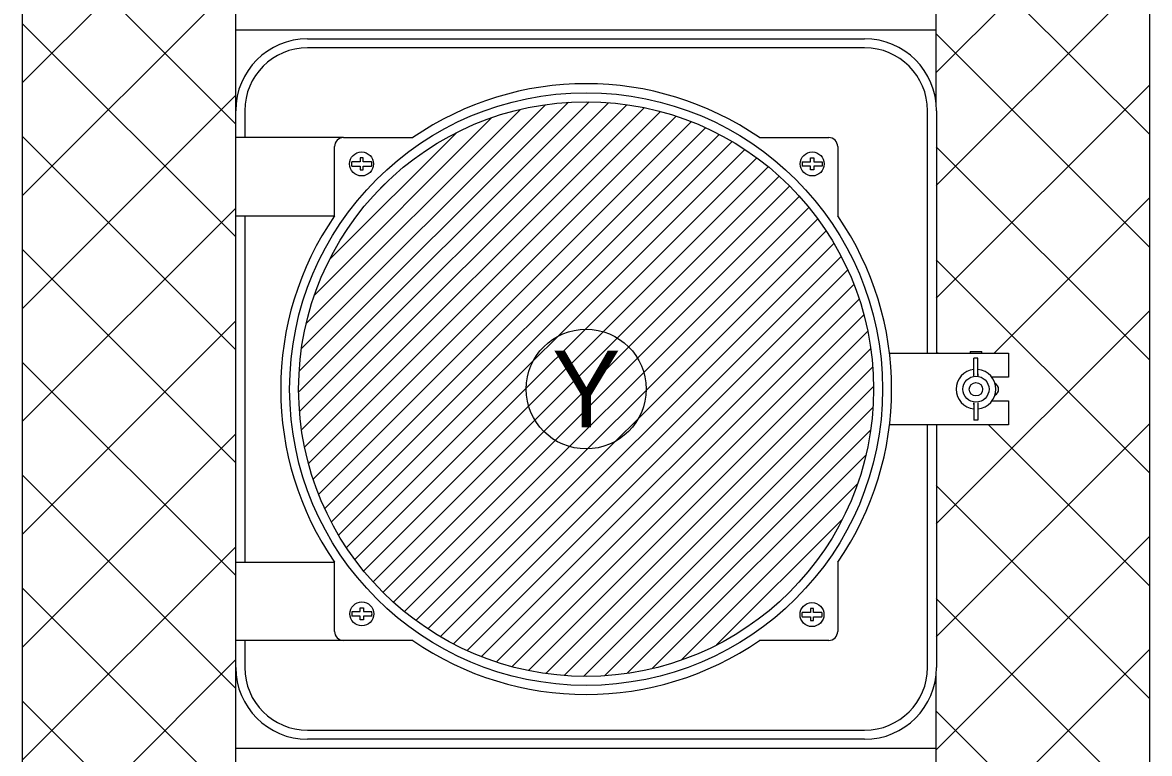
# Model space of a CAD drawing. Extents: x 99862 to 103680, y 99470 to 105076.
# Drawn here: x 101307.4 to 101519.1, y 104763.1 to 104900.5 of the extents above; entities that cross this region are included whole.
import ezdxf

# ---------------------------------------------------------------- set-up
doc = ezdxf.new("R2010")
doc.units = 0
for name, color, linetype in [('Level 1', 7, 'Continuous'), ('Level 12', 7, 'Continuous'), ('Level 18', 7, 'Continuous'), ('Level 20', 7, 'Continuous'), ('Level 4', 7, 'Continuous')]:
    doc.layers.add(name, color=color, linetype=linetype)

msp = doc.modelspace()

# ---------------------------------------------------------------- linework, layer by layer
at = {"layer": 'Level 1'}
for p, q in [((101307.44, 104609.1), (101307.44, 105054.1)), ((101519.12, 105054.1), (101519.12, 104609.1)), ((101347.44, 105034.1), (101347.44, 104629.1)), ((101307.44, 104889.18), (101347.44, 104929.18)), ((101479.07, 104891.1), (101519.12, 104931.15)), ((101347.44, 104881.46), (101307.44, 104921.46)), ((101519.12, 104879.49), (101479.07, 104919.54)), ((101479.07, 104899.1), (101479.07, 104913.14)), ((101307.44, 104867.97), (101347.44, 104907.97)), ((101479.07, 104869.88), (101519.12, 104909.93)), ((101347.44, 104860.25), (101307.44, 104900.25)), ((101347.44, 104899.1), (101479.07, 104899.1)), ((101360.99, 104897.41), (101465.62, 104897.41)), ((101479.07, 104885.06), (101479.07, 104899.1)), ((101519.12, 104858.28), (101479.07, 104898.33)), ((101465.62, 104895.73), (101360.99, 104895.73)), ((101307.44, 104846.75), (101347.44, 104886.75)), ((101479.07, 104848.67), (101519.12, 104888.72)), ((101349.18, 104883.91), (101349.18, 104878.85)), ((101477.43, 104838.35), (101477.43, 104883.91)), ((101479.12, 104883.91), (101479.12, 104838.35)), ((101347.44, 104839.03), (101307.44, 104879.03)), ((101367.74, 104878.85), (101347.44, 104878.85)), ((101367.74, 104878.85), (101380.76, 104878.85)), ((101445.85, 104878.85), (101458.87, 104878.85)), ((101366.06, 104864.15), (101366.06, 104877.16)), ((101460.56, 104877.16), (101460.56, 104864.15)), ((101519.12, 104837.07), (101479.07, 104877.12)), ((101489.96, 104838.35), (101519.12, 104867.51)), ((101307.44, 104825.54), (101347.44, 104865.54)), ((101347.44, 104864.15), (101366.06, 104864.15)), ((101349.18, 104864.15), (101349.18, 104799.05)), ((101347.44, 104817.82), (101307.44, 104857.82)), ((101519.12, 104815.85), (101479.07, 104855.9)), ((101479.07, 104806.25), (101519.12, 104846.29)), ((101307.44, 104804.33), (101347.44, 104844.33)), ((101470.28, 104838.35), (101478.24, 104838.35)), ((101478.31, 104838.35), (101492.62, 104838.35)), ((101479.12, 104838.4), (101479.24, 104838.4)), ((101479.24, 104838.35), (101479.24, 104838.4)), ((101479.24, 104838.4), (101479.4, 104838.4)), ((101479.4, 104838.35), (101479.4, 104838.4)), ((101480.88, 104838.35), (101480.88, 104838.4)), ((101492.6, 104838.35), (101492.6, 104838.4)), ((101492.62, 104838.35), (101492.62, 104833.85)), ((101347.44, 104796.61), (101307.44, 104836.61)), ((101492.62, 104833.85), (101489.48, 104833.85)), ((101489.57, 104829.4), (101492.62, 104829.4)), ((101492.62, 104829.4), (101492.62, 104824.85)), ((101478.24, 104824.85), (101470.28, 104824.85)), ((101477.43, 104779.29), (101477.43, 104824.85)), ((101492.62, 104824.85), (101478.31, 104824.85)), ((101479.07, 104785.03), (101519.12, 104825.08)), ((101479.12, 104824.85), (101479.12, 104779.29)), ((101519.12, 104794.64), (101488.91, 104824.85)), ((101307.44, 104783.11), (101347.44, 104823.11)), ((101347.44, 104775.39), (101307.44, 104815.39)), ((101519.12, 104773.43), (101479.07, 104813.48)), ((101479.07, 104763.82), (101519.12, 104803.87)), ((101307.44, 104761.9), (101347.44, 104801.9)), ((101347.44, 104799.05), (101366.06, 104799.05)), ((101366.06, 104786.04), (101366.06, 104799.05)), ((101460.56, 104799.05), (101460.56, 104786.04)), ((101347.44, 104754.18), (101307.44, 104794.18)), ((101519.12, 104752.21), (101479.07, 104792.26)), ((101367.74, 104784.35), (101347.44, 104784.35)), ((101349.18, 104784.35), (101349.18, 104779.29)), ((101380.76, 104784.35), (101367.74, 104784.35)), ((101458.87, 104784.35), (101445.85, 104784.35)), ((101479.07, 104742.61), (101519.12, 104782.65)), ((101307.44, 104740.69), (101347.44, 104780.69)), ((101479.07, 104764.1), (101479.07, 104778.14)), ((101347.44, 104732.97), (101307.44, 104772.97)), ((101519.12, 104731), (101479.07, 104771.05)), ((101360.99, 104767.48), (101465.62, 104767.48)), ((101347.44, 104764.1), (101479.07, 104764.1)), ((101465.62, 104765.79), (101360.99, 104765.79)), ((101479.07, 104750.06), (101479.07, 104764.1))]:
    msp.add_line(p, q, dxfattribs=at)
for radius in [55.69, 54]:
    msp.add_circle((101413.31, 104831.6), radius, dxfattribs=at)
for centre, radius, start, end in [((101360.99, 104883.91), 13.5, 90, 180), ((101465.62, 104883.91), 13.5, 0, 90), ((101360.99, 104883.91), 11.81, 90, 180), ((101465.62, 104883.91), 11.81, 0, 90), ((101413.31, 104831.6), 57.38, 55.4397, 124.5603), ((101367.74, 104877.16), 1.69, 90, 180), ((101458.87, 104877.16), 1.69, 0, 90), ((101413.31, 104831.6), 57.38, 145.4397, 214.5603), ((101413.31, 104831.6), 57.38, 325.4397, 34.5603), ((101367.74, 104786.04), 1.69, 180, 270), ((101458.87, 104786.04), 1.69, 270, 0), ((101413.31, 104831.6), 57.38, 235.4397, 304.5603), ((101360.99, 104779.29), 13.5, 180, 270), ((101360.99, 104779.29), 11.81, 180, 270), ((101465.62, 104779.29), 13.5, 270, 0), ((101465.62, 104779.29), 11.81, 270, 0)]:
    msp.add_arc(centre, radius, start, end, dxfattribs=at)
at = {"layer": 'Level 12'}
for p, q in [((101359.31, 104831.02), (101413.88, 104885.59)), ((101359.42, 104834.95), (101409.97, 104885.5)), ((101359.48, 104827.37), (101417.52, 104885.41)), ((101359.86, 104823.93), (101420.96, 104885.03)), ((101359.87, 104839.21), (101405.7, 104885.04)), ((101360.43, 104820.68), (101424.21, 104884.46)), ((101360.74, 104843.91), (101400.99, 104884.15)), ((101361.16, 104817.59), (101427.3, 104883.73)), ((101362.04, 104814.66), (101430.24, 104882.85)), ((101362.32, 104849.29), (101395.62, 104882.6)), ((101363.07, 104811.86), (101433.05, 104881.84)), ((101364.21, 104809.18), (101435.74, 104880.71)), ((101365.12, 104855.92), (101388.99, 104879.79)), ((101365.46, 104806.62), (101438.3, 104879.46)), ((101366.82, 104804.16), (101440.75, 104878.09)), ((101368.28, 104801.8), (101443.09, 104876.61)), ((101369.85, 104799.56), (101445.34, 104875.04)), ((101371.53, 104797.42), (101447.5, 104873.38)), ((101373.3, 104795.37), (101449.56, 104871.62)), ((101374.22, 104868.84), (101376.33, 104870.94)), ((101375.16, 104793.41), (101451.5, 104869.75)), ((101377.11, 104791.54), (101453.35, 104867.78)), ((101379.17, 104789.78), (101455.12, 104865.73)), ((101381.33, 104788.12), (101456.8, 104863.59)), ((101383.58, 104786.55), (101458.37, 104861.34)), ((101385.93, 104785.08), (101459.83, 104858.98)), ((101388.37, 104783.71), (101461.18, 104856.52)), ((101390.94, 104782.46), (101462.43, 104853.95)), ((101393.63, 104781.33), (101463.57, 104851.27)), ((101396.44, 104780.33), (101464.59, 104848.47)), ((101399.39, 104779.45), (101465.47, 104845.54)), ((101402.48, 104778.73), (101466.2, 104842.45)), ((101405.73, 104778.16), (101466.76, 104839.19)), ((101409.18, 104777.79), (101467.14, 104835.75)), ((101412.82, 104777.61), (101467.3, 104832.09)), ((101416.74, 104777.71), (101467.18, 104828.15)), ((101421.02, 104778.18), (101466.72, 104823.88)), ((101425.74, 104779.08), (101465.84, 104819.18)), ((101431.14, 104780.66), (101464.25, 104813.76)), ((101437.81, 104783.51), (101461.4, 104807.1))]:
    msp.add_line(p, q, dxfattribs=at)
at = {"layer": 'Level 18'}
msp.add_circle((101413.31, 104831.6), 11.25, dxfattribs=at)
at = {"layer": 'Level 4'}
for p, q in [((101485.42, 104838.63), (101487.64, 104838.63)), ((101485.42, 104838.63), (101485.42, 104838.4)), ((101487.64, 104838.63), (101487.64, 104838.63)), ((101487.64, 104838.4), (101487.64, 104838.63)), ((101486.15, 104835.54), (101486.15, 104837.38)), ((101486.91, 104837.38), (101486.15, 104837.38)), ((101486.91, 104835.54), (101486.91, 104837.38)), ((101486.15, 104834.73), (101486.15, 104835.54)), ((101486.15, 104834.14), (101486.15, 104834.73)), ((101486.91, 104834.73), (101486.91, 104835.54)), ((101486.91, 104834.14), (101486.91, 104834.73)), ((101486.15, 104829), (101486.15, 104828.4)), ((101486.15, 104828.4), (101486.15, 104827.59)), ((101486.15, 104827.59), (101486.15, 104825.75)), ((101486.91, 104829), (101486.91, 104828.4)), ((101486.91, 104828.4), (101486.91, 104827.59)), ((101486.91, 104827.59), (101486.91, 104825.75)), ((101486.91, 104825.75), (101486.15, 104825.75))]:
    msp.add_line(p, q, dxfattribs=at)
for centre, radius in [((101371.13, 104873.9), 2.25), ((101455.78, 104873.9), 2.25), ((101486.53, 104831.57), 2.45), ((101486.53, 104831.55), 1.25), ((101371.18, 104789.35), 2.25), ((101455.73, 104789.21), 2.25)]:
    msp.add_circle(centre, radius, dxfattribs=at)
for centre, radius, start, end in [((101371.13, 104873.9), 1.91, 167.4639, 192.4931), ((101371.13, 104873.9), 1.91, 347.5069, 12.5361), ((101455.78, 104873.9), 1.91, 167.4639, 192.4931), ((101455.78, 104873.9), 1.91, 347.5069, 12.5361), ((101486.53, 104831.57), 3.73, 95.8352, 264.1648), ((101486.53, 104831.57), 2.89, 97.5642, 97.5998), ((101486.53, 104831.57), 3.73, 275.8352, 84.1648), ((101486.53, 104831.57), 2.89, 82.4002, 82.4567), ((101489.54, 104831.55), 1.25, 295.8954, 63.3748), ((101486.53, 104831.57), 2.89, 262.4002, 262.4483), ((101486.53, 104831.57), 2.89, 277.5551, 277.5998), ((101371.18, 104789.35), 1.91, 167.5069, 192.5361), ((101371.18, 104789.35), 1.91, 347.4639, 12.4931), ((101455.73, 104789.21), 1.91, 167.5069, 192.5361), ((101455.73, 104789.21), 1.91, 347.4639, 12.4931)]:
    msp.add_arc(centre, radius, start, end, dxfattribs=at)
for points, degree in [([(101370.84, 104874.31), (101370.8, 104874.31), (101370.76, 104874.31), (101370.71, 104874.31), (101370.44, 104874.31), (101370.16, 104874.31), (101369.9, 104874.31), (101369.67, 104874.31), (101369.45, 104874.31), (101369.27, 104874.31)], 3), ([(101371.44, 104875.02), (101371.34, 104875.02), (101371.24, 104875.02), (101371.14, 104875.02), (101371.04, 104875.02), (101370.94, 104875.02), (101370.84, 104875.02)], 3), ([(101370.84, 104875.02), (101370.84, 104874.92), (101370.84, 104874.81), (101370.84, 104874.69), (101370.84, 104874.57), (101370.84, 104874.44), (101370.84, 104874.31)], 3), ([(101371.44, 104874.31), (101371.44, 104874.55), (101371.44, 104874.8), (101371.44, 104875.02)], 2), ([(101372.99, 104874.31), (101372.85, 104874.31), (101372.68, 104874.31), (101372.5, 104874.31), (101372.28, 104874.31), (101372.04, 104874.31), (101371.8, 104874.31), (101371.68, 104874.31), (101371.56, 104874.31), (101371.44, 104874.31)], 3), ([(101453.91, 104874.31), (101454.06, 104874.31), (101454.23, 104874.31), (101454.4, 104874.31), (101454.62, 104874.31), (101454.86, 104874.31), (101455.11, 104874.31), (101455.23, 104874.31), (101455.35, 104874.31), (101455.47, 104874.31)], 3), ([(101455.47, 104874.31), (101455.47, 104874.55), (101455.47, 104874.8), (101455.47, 104875.02)], 2), ([(101455.47, 104875.02), (101455.57, 104875.02), (101455.67, 104875.02), (101455.77, 104875.02), (101455.87, 104875.02), (101455.97, 104875.02), (101456.07, 104875.02)], 3), ([(101456.07, 104875.02), (101456.07, 104874.92), (101456.07, 104874.81), (101456.07, 104874.69), (101456.07, 104874.57), (101456.07, 104874.44), (101456.07, 104874.31)], 3), ([(101456.07, 104874.31), (101456.11, 104874.31), (101456.15, 104874.31), (101456.19, 104874.31), (101456.47, 104874.31), (101456.75, 104874.31), (101457, 104874.31), (101457.24, 104874.31), (101457.46, 104874.31), (101457.64, 104874.31)], 3), ([(101369.27, 104873.49), (101369.41, 104873.49), (101369.57, 104873.49), (101369.75, 104873.49), (101369.97, 104873.49), (101370.21, 104873.49), (101370.46, 104873.49), (101370.58, 104873.49), (101370.71, 104873.49), (101370.84, 104873.49)], 3), ([(101370.84, 104873.49), (101370.84, 104873.24), (101370.84, 104873), (101370.84, 104872.77)], 2), ([(101370.84, 104872.77), (101370.94, 104872.77), (101371.04, 104872.77), (101371.14, 104872.77), (101371.24, 104872.77), (101371.34, 104872.77), (101371.44, 104872.77)], 3), ([(101371.44, 104873.49), (101371.47, 104873.49), (101371.51, 104873.49), (101371.54, 104873.49), (101371.82, 104873.49), (101372.1, 104873.49), (101372.35, 104873.49), (101372.59, 104873.49), (101372.81, 104873.49), (101372.99, 104873.49)], 3), ([(101371.44, 104872.77), (101371.44, 104872.88), (101371.44, 104872.99), (101371.44, 104873.1), (101371.44, 104873.23), (101371.44, 104873.36), (101371.44, 104873.49)], 3), ([(101455.47, 104873.49), (101455.43, 104873.49), (101455.4, 104873.49), (101455.36, 104873.49), (101455.09, 104873.49), (101454.81, 104873.49), (101454.55, 104873.49), (101454.32, 104873.49), (101454.1, 104873.49), (101453.91, 104873.49)], 3), ([(101455.47, 104872.77), (101455.47, 104872.88), (101455.47, 104872.99), (101455.47, 104873.1), (101455.47, 104873.23), (101455.47, 104873.36), (101455.47, 104873.49)], 3), ([(101456.07, 104872.77), (101455.97, 104872.77), (101455.87, 104872.77), (101455.77, 104872.77), (101455.67, 104872.77), (101455.57, 104872.77), (101455.47, 104872.77)], 3), ([(101457.64, 104873.49), (101457.5, 104873.49), (101457.33, 104873.49), (101457.15, 104873.49), (101456.94, 104873.49), (101456.69, 104873.49), (101456.45, 104873.49), (101456.32, 104873.49), (101456.2, 104873.49), (101456.07, 104873.49)], 3), ([(101456.07, 104873.49), (101456.07, 104873.24), (101456.07, 104873), (101456.07, 104872.77)], 2), ([(101486.15, 104834.1), (101486.15, 104834.14), (101486.15, 104834.19), (101486.15, 104834.23), (101486.15, 104834.26), (101486.15, 104834.3), (101486.15, 104834.33), (101486.15, 104834.36), (101486.15, 104834.38), (101486.15, 104834.4), (101486.15, 104834.42), (101486.15, 104834.43), (101486.15, 104834.43), (101486.15, 104834.43), (101486.15, 104834.43), (101486.15, 104834.42), (101486.15, 104834.42), (101486.15, 104834.41), (101486.15, 104834.41)], 3), ([(101486.15, 104834.14), (101486.15, 104834.23), (101486.15, 104834.32), (101486.15, 104834.41)], 2), ([(101486.91, 104834.41), (101486.91, 104834.43), (101486.91, 104834.43), (101486.91, 104834.43), (101486.91, 104834.43), (101486.91, 104834.42), (101486.91, 104834.41), (101486.91, 104834.39), (101486.91, 104834.37), (101486.91, 104834.35), (101486.91, 104834.32), (101486.91, 104834.29), (101486.91, 104834.25), (101486.91, 104834.21), (101486.91, 104834.17), (101486.91, 104834.13), (101486.91, 104834.12), (101486.91, 104834.11), (101486.91, 104834.1)], 3), ([(101486.91, 104834.14), (101486.91, 104834.23), (101486.91, 104834.32), (101486.91, 104834.41)], 2), ([(101486.15, 104828.72), (101486.15, 104828.71), (101486.15, 104828.7), (101486.15, 104828.7), (101486.15, 104828.7), (101486.15, 104828.71), (101486.15, 104828.72), (101486.15, 104828.74), (101486.15, 104828.76), (101486.15, 104828.79), (101486.15, 104828.81), (101486.15, 104828.85), (101486.15, 104828.88), (101486.15, 104828.92), (101486.15, 104828.96), (101486.15, 104829), (101486.15, 104829.01), (101486.15, 104829.02), (101486.15, 104829.03)], 3), ([(101486.15, 104829), (101486.15, 104828.9), (101486.15, 104828.81), (101486.15, 104828.72)], 2), ([(101486.91, 104829.03), (101486.91, 104828.99), (101486.91, 104828.95), (101486.91, 104828.91), (101486.91, 104828.87), (101486.91, 104828.83), (101486.91, 104828.8), (101486.91, 104828.77), (101486.91, 104828.75), (101486.91, 104828.73), (101486.91, 104828.72), (101486.91, 104828.71), (101486.91, 104828.7), (101486.91, 104828.7), (101486.91, 104828.7), (101486.91, 104828.71), (101486.91, 104828.72), (101486.91, 104828.72), (101486.91, 104828.72)], 3), ([(101486.91, 104829), (101486.91, 104828.9), (101486.91, 104828.81), (101486.91, 104828.72)], 2), ([(101369.32, 104789.77), (101369.46, 104789.77), (101369.62, 104789.77), (101369.8, 104789.77), (101370.02, 104789.77), (101370.26, 104789.77), (101370.51, 104789.77), (101370.63, 104789.77), (101370.76, 104789.77), (101370.89, 104789.77)], 3), ([(101370.89, 104790.48), (101370.99, 104790.48), (101371.09, 104790.48), (101371.19, 104790.48), (101371.29, 104790.48), (101371.39, 104790.48), (101371.49, 104790.48)], 3), ([(101370.89, 104789.77), (101370.89, 104790.01), (101370.89, 104790.25), (101370.89, 104790.48)], 2), ([(101371.49, 104790.48), (101371.49, 104790.37), (101371.49, 104790.26), (101371.49, 104790.15), (101371.49, 104790.02), (101371.49, 104789.89), (101371.49, 104789.77)], 3), ([(101371.49, 104789.77), (101371.52, 104789.77), (101371.56, 104789.77), (101371.59, 104789.77), (101371.87, 104789.77), (101372.15, 104789.77), (101372.4, 104789.77), (101372.64, 104789.77), (101372.86, 104789.77), (101373.04, 104789.77)], 3), ([(101455.42, 104789.62), (101455.38, 104789.62), (101455.35, 104789.62), (101455.32, 104789.62), (101455.04, 104789.62), (101454.76, 104789.62), (101454.5, 104789.62), (101454.27, 104789.62), (101454.05, 104789.62), (101453.87, 104789.62)], 3), ([(101455.42, 104790.33), (101455.42, 104790.22), (101455.42, 104790.11), (101455.42, 104790), (101455.42, 104789.88), (101455.42, 104789.75), (101455.42, 104789.62)], 3), ([(101456.02, 104790.33), (101455.92, 104790.33), (101455.82, 104790.33), (101455.72, 104790.33), (101455.62, 104790.33), (101455.52, 104790.33), (101455.42, 104790.33)], 3), ([(101456.02, 104789.62), (101456.02, 104789.86), (101456.02, 104790.11), (101456.02, 104790.33)], 2), ([(101457.59, 104789.62), (101457.45, 104789.62), (101457.28, 104789.62), (101457.11, 104789.62), (101456.89, 104789.62), (101456.64, 104789.62), (101456.4, 104789.62), (101456.27, 104789.62), (101456.15, 104789.62), (101456.02, 104789.62)], 3), ([(101370.89, 104788.94), (101370.85, 104788.94), (101370.8, 104788.94), (101370.76, 104788.94), (101370.48, 104788.94), (101370.2, 104788.94), (101369.95, 104788.94), (101369.72, 104788.94), (101369.5, 104788.94), (101369.32, 104788.94)], 3), ([(101370.89, 104788.23), (101370.89, 104788.34), (101370.89, 104788.45), (101370.89, 104788.56), (101370.89, 104788.68), (101370.89, 104788.81), (101370.89, 104788.94)], 3), ([(101371.49, 104788.23), (101371.39, 104788.23), (101371.29, 104788.23), (101371.19, 104788.23), (101371.09, 104788.23), (101370.99, 104788.23), (101370.89, 104788.23)], 3), ([(101373.04, 104788.94), (101372.9, 104788.94), (101372.73, 104788.94), (101372.55, 104788.94), (101372.33, 104788.94), (101372.09, 104788.94), (101371.84, 104788.94), (101371.73, 104788.94), (101371.61, 104788.94), (101371.49, 104788.94)], 3), ([(101371.49, 104788.94), (101371.49, 104788.7), (101371.49, 104788.45), (101371.49, 104788.23)], 2), ([(101453.87, 104788.79), (101454.01, 104788.79), (101454.18, 104788.79), (101454.36, 104788.79), (101454.57, 104788.79), (101454.82, 104788.79), (101455.06, 104788.79), (101455.18, 104788.79), (101455.3, 104788.79), (101455.42, 104788.79)], 3), ([(101455.42, 104788.79), (101455.42, 104788.55), (101455.42, 104788.31), (101455.42, 104788.08)], 2), ([(101455.42, 104788.08), (101455.52, 104788.08), (101455.62, 104788.08), (101455.72, 104788.08), (101455.82, 104788.08), (101455.92, 104788.08), (101456.02, 104788.08)], 3), ([(101456.02, 104788.79), (101456.06, 104788.79), (101456.1, 104788.79), (101456.14, 104788.79), (101456.42, 104788.79), (101456.7, 104788.79), (101456.96, 104788.79), (101457.19, 104788.79), (101457.41, 104788.79), (101457.59, 104788.79)], 3), ([(101456.02, 104788.08), (101456.02, 104788.19), (101456.02, 104788.3), (101456.02, 104788.41), (101456.02, 104788.54), (101456.02, 104788.66), (101456.02, 104788.79)], 3)]:
    msp.add_open_spline(points, degree=degree, dxfattribs=at)

# ---------------------------------------------------------------- texts
at = {"layer": 'Level 20'}
msp.add_text('Y', height=14.4, dxfattribs=at).set_placement((101406.92, 104824.4))

doc.saveas('drawing.dxf')
